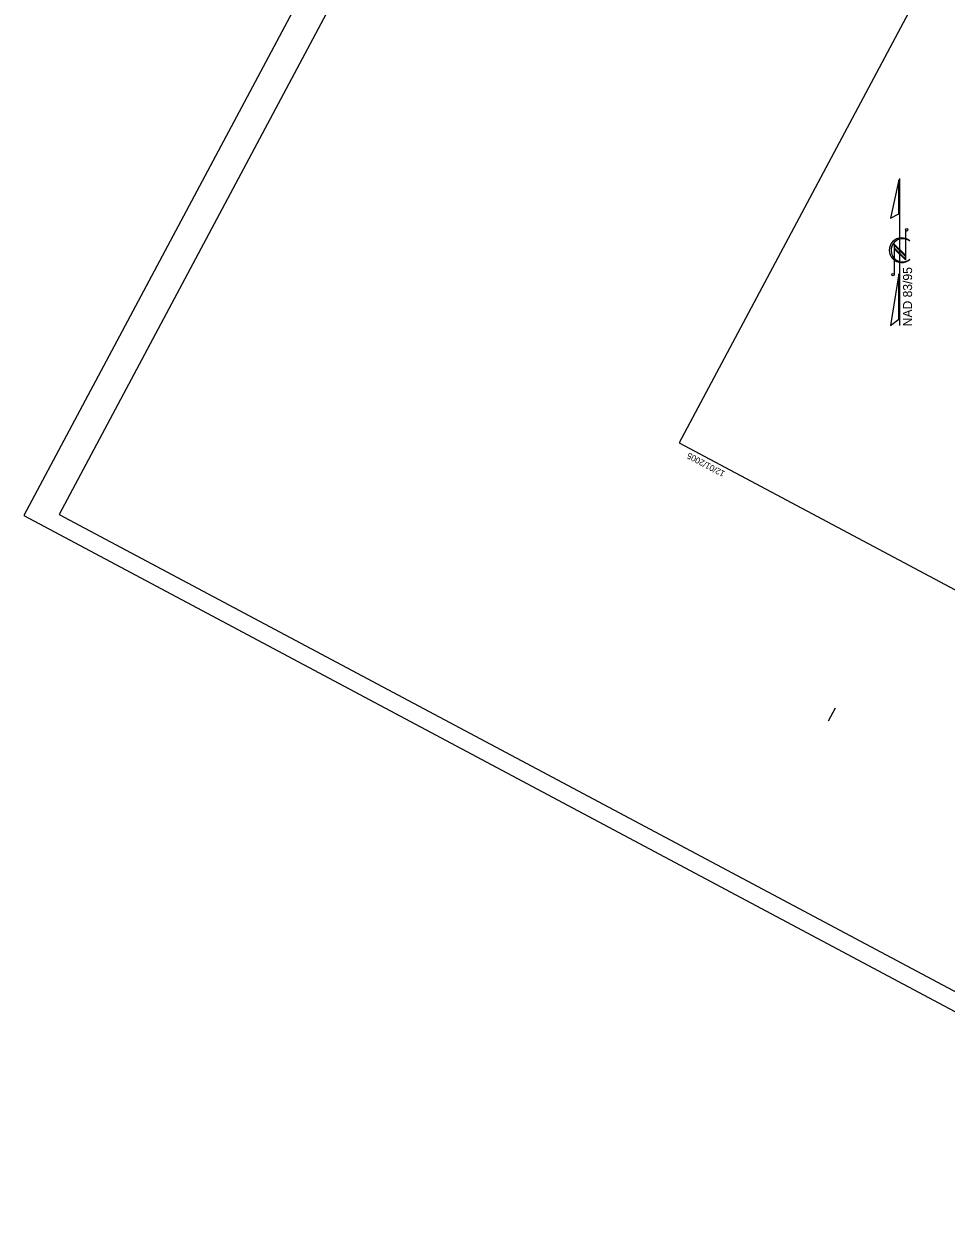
# Model space of a CAD drawing. Extents: x 1970823 to 1988115, y 770601 to 786368.
# Drawn here: x 1970823 to 1974901, y 774347 to 779627 of the extents above; entities that cross this region are included whole.
import ezdxf

# ---------------------------------------------------------------- set-up
doc = ezdxf.new("R2010")
doc.units = 0
for name, color, linetype in [('CTL Sheet Border CELL', 7, 'Continuous'), ('Old_Level_1', 7, 'Continuous'), ('Old_Level_11', 7, 'Continuous'), ('Old_Level_50', 7, 'Continuous'), ('Old_Level_51', 7, 'Continuous'), ('Sheet Data Field CELL', 7, 'Continuous')]:
    doc.layers.add(name, color=color, linetype=linetype)

msp = doc.modelspace()

# ---------------------------------------------------------------- linework, layer by layer
at = {"layer": 'CTL Sheet Border CELL'}
msp.add_lwpolyline([(1977401.8, 784679.3), (1973721.3, 777772.6), (1978555.9, 775196.3), (1982236.4, 782102.9)], close=True, dxfattribs=at)
at = {"layer": 'Old_Level_1'}
for p, q in [((1974697.4, 778291.8), (1974697.4, 778941.8)), ((1974721.9, 778715.6), (1974721.9, 778582.2)), ((1974721.9, 778603), (1974672.2, 778652.7)), ((1974672.2, 778652.7), (1974672.2, 778517.1)), ((1974721.9, 778598.1), (1974672.2, 778647.8)), ((1974672.2, 778647.8), (1974672.2, 778635.6)), ((1974721.9, 778585.9), (1974672.2, 778635.6)), ((1974672.2, 778635.6), (1974721.9, 778585.9)), ((1974721.9, 778582.2), (1974672.2, 778631.9)), ((1974740.3, 778665.9), (1974741, 778665.4)), ((1974721.9, 778585.9), (1974721.9, 778598.1))]:
    msp.add_line(p, q, dxfattribs=at)
for points in [[(1974692.9, 778936.1), (1974655.8, 778767.3), (1974692.9, 778786.1)], [(1974692.1, 778520.8), (1974655.3, 778291.8), (1974692.1, 778320.8)]]:
    msp.add_lwpolyline(points, close=True, dxfattribs=at)
for centre in [(1974727.2, 778715.5), (1974666.9, 778516.9)]:
    msp.add_circle(centre, 5.3, dxfattribs=at)
for centre, radius, start, end in [((1974704.3, 778625), 54.6, 47.84, 312.3941), ((1974709.6, 778625), 51.2, 53.095, 308.6287)]:
    msp.add_arc(centre, radius, start, end, dxfattribs=at)
at = {"layer": 'Old_Level_50'}
msp.add_lwpolyline([(1975680.9, 786280.6), (1970978.5, 777456.3), (1976565.4, 774479.1), (1981267.8, 783303.4)], close=True, dxfattribs=at)
at = {"layer": 'Old_Level_51'}
msp.add_lwpolyline([(1975574.8, 786367.7), (1970823, 777450.8), (1976647.6, 774346.9), (1981399.3, 783263.8)], close=True, dxfattribs=at)
at = {"layer": 'Sheet Data Field CELL'}
msp.add_line((1974381.4, 776543), (1974412, 776600.5), dxfattribs=at)

# ---------------------------------------------------------------- texts
at = {"layer": 'Old_Level_11'}
msp.add_text('NAD 83/95', height=40, rotation=90, dxfattribs=at).set_placement((1974750.9, 778288.7))
at = {"layer": 'Sheet Data Field CELL'}
msp.add_text('12/01/2005', height=27.39, rotation=151.9471, dxfattribs=at).set_placement((1973926.4, 777644.8))

doc.saveas('drawing.dxf')
